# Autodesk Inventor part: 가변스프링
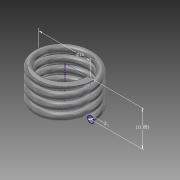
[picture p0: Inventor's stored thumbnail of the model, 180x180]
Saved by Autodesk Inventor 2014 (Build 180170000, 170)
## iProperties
Created: 2015-04
Part Number: 가변스프링
Material: 강철, 탄소
Document SubType Name: Modeling
Designer: basic
Mass: 4.77516 g
Surface Area: 12.5185 cm^2
Volume: 0.606755 cm^3
Density: 7.87 g/cm^3
Appearance: 반연마
Author: basic
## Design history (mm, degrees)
sketch "스케치1"
  geometry: L1 (0, 0)-(-8, 0); L2 (-8, 0)-(-8, 11.05); L3 (-8, 11.05)-(0, 11.05); L4 (0, 11.05)-(0, 0); C1 r 1 at (-8, 0)
  constraints: 8 end point, 2 parallel, 1 centre point, 1 coincident, 1 horizontal, 1 perpendicular
  dimensions: "d0" = 2 diameter of C1; "d1" = 11.05025 distance between parallel lines of L1 L3 (derived); "d2" = 16 diameter of L2 L4
feature "코일1" sketch "스케치1" pitch "d3" = 10; turns "d5" = 4; dims "d4" = 11.05025 (= d1), "d6" = 0, angle "d7" = 90 deg, angle "d8" = 90 deg, "d9" = 0, "d10" = 0
sketch "스케치2"
  geometry: L1 (9, 0)-(7, 0) reference; 1 further point
  constraints: 1 horizontal alignment
extrude "돌출1" cut sketch "스케치2" distance "d11" = 10; taper "d12" = 0 deg
node "작업 평면1"
sketch "스케치3"
  geometry: L1 (1, 0)-(-1, 0) reference; 1 further point
  constraints: 1 horizontal alignment
extrude "돌출2" cut sketch "스케치3" distance "d14" = 10; taper "d15" = 0 deg
node "솔리드1"
node "절단 모서리 투영1"
node "절단 모서리 투영2"
other parameters: "d13" = 0
